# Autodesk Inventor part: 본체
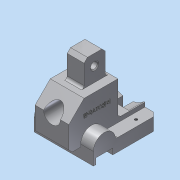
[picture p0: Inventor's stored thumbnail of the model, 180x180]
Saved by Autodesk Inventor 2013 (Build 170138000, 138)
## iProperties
Created: 2016-11
Part Number: 본체
Material: 알루미늄 6061
Document SubType Name: Modeling
Designer: dgall
Density: 2.71 g/cm^3
Mass: 463.602 g
Surface Area: 317.215 cm^2
Volume: 171.071 cm^3
Author: dgall
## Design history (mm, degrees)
sketch "스케치1"
  geometry: L1 (-13, 0)-(-13, -15); L2 (-13, -15)-(-10, -15); L3 (-10, -15)-(-10, -8); L4 (-10, -8)-(10, -8); L5 (10, -8)-(10, -15); L6 (10, -15)-(63, -15); L7 (63, -15)-(63, 0); L8 (63, 0)-(13, 0); A1 r 13 centre (0, 0) between (13, 0) and (-13, 0); 1 further point
  constraints: 16 end point, 5 parallel, 2 horizontal alignment, 2 point on circle, 1 centre point, 1 coincident, 1 collinear, 1 perpendicular, 1 tangent, 1 vertical
  dimensions: "d0" = 26 diameter of A1; "d1" = 3 distance of L1.end L2.end; "d2" = 20 distance of L3.end L4.end; "d3" = 63 horizontal distance of L6.end point (0, 0); "d4" = 7 distance of L2.end L3.end; "d5" = 15 distance of L6.end L7.end
extrude "돌출1" new body sketch "스케치1" distance "d6" = 15; taper "d7" = 0 deg
node "작업 평면1"
sketch "스케치2"
  geometry: L1 (0, 13)-(0, 63) reference; L2 (0, 63)-(-15, 63) reference; L3 (-15, 63)-(-15, 10) reference; L4 (-15, 10)-(-8, 10) reference; L5 (-8, 10)-(-8, -10) reference; L6 (-8, -10)-(-15, -10) reference; L7 (-15, -10)-(-15, -13) reference; L8 (-15, -13)-(0, -13) reference; A1 r 13 centre (0, 0) between (0, -13) and (0, 13) reference; 1 further point
extrude "돌출2" join sketch "스케치2" distance "d9" = 15; taper "d10" = 0 deg
sketch "스케치3"
  geometry: L1 (15, -13)-(0, -13) reference; L2 (15, -10)-(15, -13) reference; L3 (8, -10)-(15, -10) reference; L4 (8, 10)-(8, -10) reference; L5 (15, 10)-(8, 10) reference; L6 (15, 63)-(15, 10) reference; L7 (-5, 63)-(-5, 31); L8 (-5, 31)-(-45, 31); L9 (-45, 31)-(-45, -9); L10 (-45, -9)-(-27, -27); L11 (-27, -27)-(3, -27); L12 (-5, 63)-(15, 63); L13 (15, 63)-(15, 11); L14 (3, -27)-(3, -13); L15 (3, -13)-(15, -13); 1 further point
  constraints: 18 end point, 4 perpendicular, 2 point on line, 1 collinear, 1 horizontal alignment, 1 vertical
  dimensions: "d11" = 45 deg angle of L9 L10; "d12" = 18 horizontal distance of L9.end L10.end; "d14" = 30 distance of L10.end L11.end; "d15" = 20 distance between parallel lines of L6 L7; "d16" = 90 distance from line of point (0, 63) L11; "d17" = 58 distance between parallel lines of L11 L8; "d18" = 60 distance between parallel lines of L6 L9
extrude "돌출3" join sketch "스케치3" distance "d21" = 40; taper "d22" = 0 deg
sketch "스케치5"
  geometry: L1 (0, 0)-(40, 0) reference; L2 (55, 60)-(-15, 60) reference; 3 further points
  constraints: 1 midpoint, 1 vertical alignment
  dimensions: "d23" = 42 distance from line of L2 point (20, 18)
hole "구멍1" sketch "스케치5" at (20, 18) diameter "d24" = 20; stored, may be unused: countersink angle "d28" = 90 deg, drill point angle "d30" = 118 deg; dims "d25" = 6, "d26" = 28, "d27" = 7, "d29" = 8
sketch "스케치6"
  geometry: L1 (0, 15)-(-70, 15) reference; L2 (-55, -5)-(-15, -5) reference; L3 (-29, 1.373)-(-29, 15); L4 (-41, 1.373)-(-41, 15); C1 r 10 at (-35, -27) reference; A1 r 29 centre (-35, -27) between (-16.106, -5) and (-29, 1.373); A2 r 29 centre (-35, -27) between (-41, 1.373) and (-53.894, -5)
  constraints: 4 end point, 4 point on circle, 4 point on line, 2 centre point, 1 coincident, 1 concentric, 1 parallel, 1 perpendicular
  dimensions: "d32" = 6 distance from line of C1.centre L4; "d33" = 6 distance from line of L3 C1.centre; "d34" = 29 radius of A1
extrude "돌출4" cut sketch "스케치6" distance "d35" = 18; taper "d36" = 0 deg
node "작업 평면2"
sketch "스케치7"
  geometry: L1 (-75, 1)-(-45, 1); L2 (-45, 1)-(-45, 26); L3 (-45, 26)-(-75, 26); L4 (-75, 26)-(-75, 1); L5 (-5, 31)-(-45, 31) reference; L6 (15, 45)-(15, 63) reference; 1 further point
  constraints: 8 end point, 2 parallel, 1 horizontal, 1 perpendicular, 1 vertical alignment
  dimensions: "d38" = 25 distance of L3.end L1.start; "d40" = 5 distance between parallel lines of L5 L3; "d41" = 90 distance between parallel lines of L6 L4
extrude "돌출5" join sketch "스케치7" distance "d42" = 20; taper "d43" = 0 deg
sketch "스케치8"
  geometry: L1 (-75, 26)-(-75, 1) reference; L2 (15, 10)-(15, 63) reference; C1 r 4 at (-62, 13.5); 2 further points
  constraints: 1 centre point, 1 horizontal alignment, 1 midpoint
  dimensions: "d44" = 8 diameter of C1; "d45" = 77 distance from line of L2 C1.centre
extrude "돌출6" cut sketch "스케치8" distance "d46" = 20; taper "d47" = 0 deg
sketch "스케치9"
  geometry: L1 (-15, 50)-(0, 50) reference; L2 (-55, 50)-(-70, 50) reference; L3 (-25, -40)-(-45, -40) reference; L4 (-16.106, 32)-(-53.894, 32) reference; L5 (-16.106, 50)-(-16.106, 32) reference; L6 (-16.106, 32)-(-53.894, 32) reference; L7 (-53.894, 32)-(-53.894, 50) reference; L8 (-55, 50)-(-53.894, 50) reference; L9 (-55, 50)-(-55, 18) reference; L10 (-55, 18)-(-15, 18) reference; L11 (-15, 50)-(-15, 18) reference; L12 (-16.106, 50)-(-15, 50) reference; L13 (0, -3)-(-70, -3) reference; L14 (-62.5, 32)-(-7.5, 32); 3 further points
  constraints: 2 end point, 2 midpoint, 1 vertical alignment
  dimensions: "d48" = 18 distance from line of L1 L14.end; "d49" = 18 distance from line of L2 L14.start; "d50" = 55 distance of L14.end L14.start
hole "구멍2" sketch "스케치9" at (-7.5, 32), (-62.5, 32) diameter "d51" = 3.242; stored, may be unused: countersink angle "d55" = 90 deg, drill point angle "d57" = 118 deg; dims "d52" = 6, "d53" = 28, "d54" = 7, "d56" = 8
fillet "모깎기1" dims "d58" = 3
chamfer "모따기1" distance "d59" = 1; stored, may be unused: second distance "d60" = 2, angle "d61" = 45 deg
chamfer "모따기2" distance "d62" = 4; stored, may be unused: second distance "d63" = 2, angle "d64" = 45 deg
chamfer "모따기3" distance "d65" = 5; stored, may be unused: second distance "d66" = 2, angle "d67" = 45 deg
sketch "스케치10"
  geometry: L1 (-8, 31)-(-45, 31) reference; 2 further points
  constraints: 1 other
  dimensions: "d68" = 25 distance from line of L1 point (-27, 6); "d69" = 18 horizontal distance of point (-45, -9) point (-27, 6)
extrude "돌출7" join sketch "스케치10" distance "d70" = 0.5; taper "d71" = 0 deg
node "솔리드1"
node "투영된 루프1"
node "투영된 루프2"
other parameters: "d31" = 58
